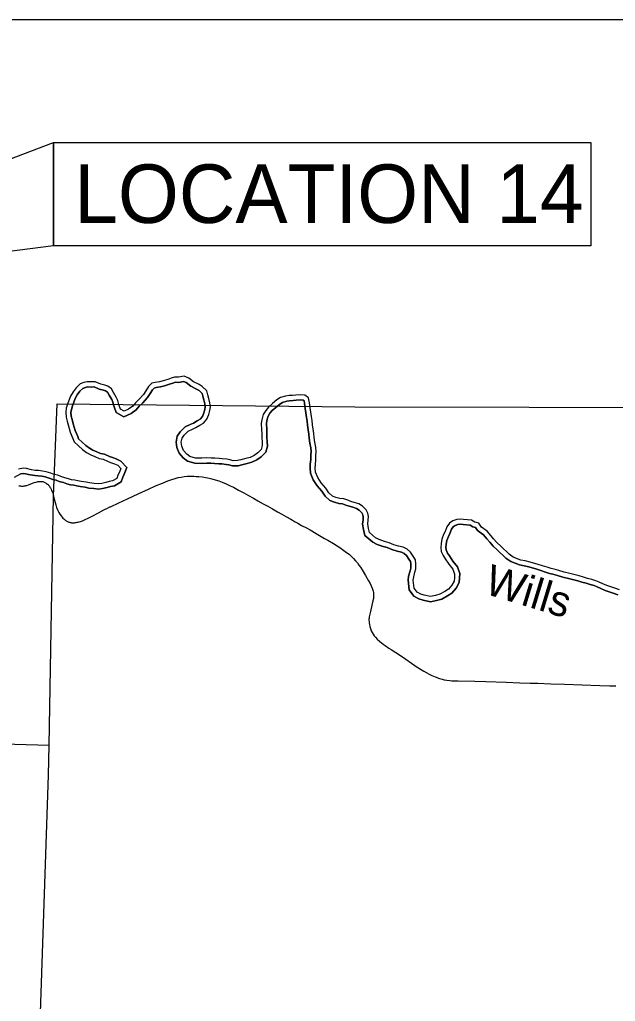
# Model space of a CAD drawing. Extents: x -12.1 to 34, y 0 to 22.
# Drawn here: x 6.151 to 7.88, y 17.456 to 20.306 of the extents above; entities that cross this region are included whole.
import ezdxf

# ---------------------------------------------------------------- set-up
doc = ezdxf.new("R2010")
doc.units = 0
for name, color, linetype in [('BR_P_Gen_Text', 7, 'Continuous'), ('GM_X_Major_River', 7, 'Continuous'), ('GM_X_Major_River_Text', 7, 'Continuous'), ('GM_X_State_Route', 7, 'Continuous'), ('GM_X_Township', 7, 'Continuous'), ('SH_Text', 7, 'Continuous')]:
    doc.layers.add(name, color=color, linetype=linetype)

msp = doc.modelspace()

# ---------------------------------------------------------------- linework, layer by layer
at = {"layer": 'BR_P_Gen_Text'}
for points in [[(6.2488, 19.9493), (6.2488, 19.649), (5.0586, 19.4964)], [(6.2488, 19.9493), (7.8089, 19.9493), (7.8089, 19.649), (6.2488, 19.649)]]:
    msp.add_lwpolyline(points, close=True, dxfattribs=at)
at = {"layer": 'GM_X_Major_River'}
for points in [[(6.8543, 19.0792), (6.8547, 19.0693), (6.8516, 19.0579), (6.8417, 19.0482), (6.8315, 19.0406), (6.8198, 19.0349), (6.8074, 19.0316), (6.7925, 19.0283), (6.7826, 19.0257), (6.7702, 19.0256), (6.7613, 19.0277), (6.7521, 19.0297), (6.7389, 19.0311), (6.7297, 19.0317), (6.7169, 19.0327), (6.7066, 19.0329), (6.6941, 19.0336), (6.6796, 19.0327), (6.6615, 19.0333), (6.6448, 19.0378), (6.6358, 19.0448), (6.6265, 19.0554), (6.6211, 19.0675), (6.6199, 19.0792), (6.622, 19.0906), (6.6283, 19.0995), (6.6403, 19.1114), (6.6523, 19.1171), (6.6625, 19.1218), (6.6735, 19.1287), (6.6841, 19.1348), (6.6943, 19.1459), (6.6999, 19.1595), (6.703, 19.1716), (6.7043, 19.1819), (6.7028, 19.1933), (6.7002, 19.206), (6.6969, 19.217), (6.6943, 19.2288), (6.6804, 19.2411), (6.6715, 19.2464), (6.6554, 19.2548), (6.6415, 19.2657), (6.628, 19.2713), (6.612, 19.2679), (6.6006, 19.2686), (6.5907, 19.2649), (6.5808, 19.2617), (6.567, 19.2573), (6.5564, 19.2547), (6.5443, 19.2525), (6.5344, 19.2503), (6.5242, 19.241), (6.5168, 19.2285), (6.5098, 19.2181), (6.4975, 19.2041), (6.4869, 19.1937), (6.4788, 19.1844), (6.4668, 19.1751), (6.4541, 19.1693), (6.4431, 19.1756), (6.4387, 19.1891), (6.4354, 19.2005), (6.4311, 19.21), (6.4231, 19.2235), (6.417, 19.2344), (6.407, 19.2422), (6.3981, 19.245), (6.386, 19.2477), (6.37, 19.2547), (6.3579, 19.2543), (6.3466, 19.2545), (6.3373, 19.253), (6.326, 19.2483), (6.3144, 19.2372), (6.3056, 19.2254), (6.2983, 19.2129), (6.2937, 19.2004), (6.2899, 19.1897), (6.2861, 19.178), (6.2844, 19.1662), (6.2853, 19.1524), (6.2889, 19.1407), (6.2918, 19.1297), (6.294, 19.119), (6.2977, 19.1084), (6.3053, 19.09), (6.3089, 19.0804), (6.3218, 19.0687), (6.3332, 19.0582), (6.345, 19.0494), (6.3568, 19.0423), (6.3689, 19.0378), (6.3814, 19.0322), (6.3928, 19.0302), (6.4056, 19.0242), (6.4148, 19.0207), (6.4255, 19.0169), (6.4355, 19.0124), (6.4445, 19.0028), (6.4403, 18.9925)], [(6.8691, 19.0799), (6.8697, 19.0676), (6.8649, 19.0501), (6.8514, 19.0368), (6.8393, 19.0279), (6.8251, 19.0209), (6.811, 19.0171), (6.796, 19.0138), (6.7846, 19.0108), (6.7685, 19.0107), (6.758, 19.0132), (6.7497, 19.015), (6.7376, 19.0162), (6.7286, 19.0169), (6.7161, 19.0178), (6.706, 19.0181), (6.6942, 19.0187), (6.6798, 19.0178), (6.6593, 19.0185), (6.6379, 19.0242), (6.6255, 19.034), (6.6139, 19.0473), (6.6065, 19.0636), (6.6049, 19.0798), (6.6079, 19.0965), (6.6169, 19.1092), (6.6316, 19.1237), (6.646, 19.1306), (6.6555, 19.135), (6.6658, 19.1414), (6.6747, 19.1466), (6.6815, 19.154), (6.6857, 19.1642), (6.6883, 19.1744), (6.6893, 19.1819), (6.6881, 19.1908), (6.6858, 19.2024), (6.6825, 19.2133), (6.6808, 19.2208), (6.6716, 19.229), (6.6642, 19.2334), (6.6473, 19.2422), (6.6339, 19.2527), (6.6265, 19.2558), (6.6131, 19.253), (6.6029, 19.2535), (6.5956, 19.2509), (6.5854, 19.2475), (6.571, 19.243), (6.5595, 19.2402), (6.5473, 19.2379), (6.5415, 19.2366), (6.5359, 19.2315), (6.5294, 19.2205), (6.5216, 19.209), (6.5083, 19.1939), (6.4978, 19.1836), (6.4891, 19.1736), (6.4746, 19.1623), (6.4533, 19.1526), (6.4307, 19.1656), (6.4245, 19.1847), (6.4214, 19.1953), (6.4178, 19.2032), (6.4102, 19.2161), (6.4055, 19.2246), (6.4, 19.2288), (6.3942, 19.2306), (6.3813, 19.2335), (6.3671, 19.2397), (6.358, 19.2394), (6.3476, 19.2396), (6.3414, 19.2386), (6.3343, 19.2357), (6.3256, 19.2273), (6.318, 19.2172), (6.3118, 19.2066), (6.3077, 19.1954), (6.304, 19.185), (6.3007, 19.1746), (6.2994, 19.1656), (6.3, 19.1551), (6.3032, 19.1448), (6.3063, 19.1331), (6.3084, 19.123), (6.3116, 19.1136), (6.3191, 19.0954), (6.3216, 19.089), (6.3318, 19.0797), (6.3428, 19.0696), (6.3533, 19.0617), (6.3633, 19.0558), (6.3746, 19.0516), (6.3858, 19.0465), (6.3973, 19.0445), (6.4113, 19.038), (6.42, 19.0347), (6.4311, 19.0307), (6.4443, 19.0247), (6.4618, 19.0061), (6.4541, 18.9869)], [(6.4539, 18.9865), (6.4618, 19.0061), (6.4443, 19.0247), (6.4311, 19.0307), (6.42, 19.0347), (6.4113, 19.038), (6.3973, 19.0445), (6.3858, 19.0465), (6.3746, 19.0516), (6.3633, 19.0558), (6.3533, 19.0617), (6.3428, 19.0696), (6.3318, 19.0797), (6.3216, 19.089), (6.3191, 19.0954), (6.3116, 19.1136), (6.3084, 19.123), (6.3063, 19.1331), (6.3032, 19.1448), (6.3, 19.1551), (6.2994, 19.1656), (6.3007, 19.1746), (6.304, 19.185), (6.3077, 19.1954), (6.3118, 19.2066), (6.318, 19.2172), (6.3256, 19.2273), (6.3343, 19.2357), (6.3414, 19.2386), (6.3476, 19.2396), (6.358, 19.2394), (6.3671, 19.2397), (6.3813, 19.2335), (6.3942, 19.2306), (6.4, 19.2288), (6.4055, 19.2246), (6.4102, 19.2161), (6.4178, 19.2032), (6.4214, 19.1953), (6.4245, 19.1847), (6.4307, 19.1656), (6.4533, 19.1526), (6.4746, 19.1623), (6.4891, 19.1736), (6.4978, 19.1836), (6.5083, 19.1939), (6.5216, 19.209), (6.5294, 19.2205), (6.5359, 19.2315), (6.5415, 19.2366), (6.5473, 19.2379), (6.5595, 19.2402), (6.571, 19.243), (6.5854, 19.2475), (6.5956, 19.2509), (6.6029, 19.2535), (6.6131, 19.253), (6.6265, 19.2558), (6.6339, 19.2527), (6.6473, 19.2422), (6.6642, 19.2334), (6.6716, 19.229), (6.6808, 19.2208), (6.6825, 19.2133), (6.6858, 19.2024), (6.6881, 19.1908), (6.6893, 19.1819), (6.6883, 19.1744), (6.6857, 19.1642), (6.6815, 19.154), (6.6747, 19.1466), (6.6658, 19.1414), (6.6555, 19.135), (6.646, 19.1306), (6.6316, 19.1237), (6.6169, 19.1092), (6.6079, 19.0965), (6.6049, 19.0798), (6.6065, 19.0636), (6.6139, 19.0473), (6.6255, 19.034), (6.6379, 19.0242), (6.6593, 19.0185), (6.6798, 19.0178), (6.6942, 19.0187), (6.706, 19.0181), (6.7161, 19.0178), (6.7286, 19.0169), (6.7376, 19.0162), (6.7497, 19.015), (6.758, 19.0132), (6.7685, 19.0107), (6.7846, 19.0108), (6.796, 19.0138), (6.811, 19.0171), (6.8251, 19.0209), (6.8393, 19.0279), (6.8514, 19.0368), (6.8649, 19.0501), (6.8697, 19.0676), (6.8691, 19.0799)], [(7.4394, 18.855), (7.4298, 18.856), (7.4199, 18.8553), (7.4078, 18.8509), (7.3983, 18.8444), (7.3906, 18.8333), (7.3857, 18.8201), (7.3815, 18.8109), (7.3767, 18.7977), (7.3739, 18.7856), (7.3729, 18.7735), (7.3741, 18.7624), (7.3799, 18.75), (7.386, 18.7408), (7.3964, 18.7253), (7.4086, 18.7104), (7.4133, 18.6962), (7.4127, 18.6859), (7.4117, 18.676), (7.4054, 18.6642), (7.3956, 18.6524), (7.3853, 18.6455), (7.3709, 18.6376), (7.3574, 18.6343), (7.3436, 18.631), (7.3254, 18.6348), (7.3151, 18.6379), (7.3048, 18.6438), (7.2958, 18.6559), (7.2935, 18.679), (7.2945, 18.6879), (7.2983, 18.7021), (7.3007, 18.7114), (7.3009, 18.7263), (7.3001, 18.7377), (7.2929, 18.748), (7.285, 18.7596), (7.2757, 18.7688), (7.2639, 18.7744), (7.2501, 18.7771), (7.2366, 18.7817), (7.223, 18.7872), (7.2102, 18.7911), (7.1945, 18.7963), (7.1838, 18.8015), (7.1663, 18.8167), (7.163, 18.8291), (7.1612, 18.8419), (7.1625, 18.8529), (7.1631, 18.8636), (7.1613, 18.8732), (7.1566, 18.8831), (7.1458, 18.8937), (7.1351, 18.9004), (7.1219, 18.9045), (7.1123, 18.9073), (7.1031, 18.9108), (7.0913, 18.9153), (7.08, 18.9163), (7.0686, 18.9191), (7.0593, 18.9226), (7.0486, 18.9324), (7.0396, 18.9462), (7.0263, 18.9614), (7.0159, 18.977), (7.0098, 18.9926), (7.0086, 19.0043), (7.0092, 19.0146), (7.0105, 19.0281), (7.0104, 19.0406), (7.0114, 19.0516), (7.0109, 19.0648), (7.008, 19.079), (7.0057, 19.0928), (7.0046, 19.1046), (7.0027, 19.117), (7.0008, 19.1301), (6.9997, 19.1422), (6.9982, 19.1536), (6.9959, 19.1667), (6.9944, 19.1791), (6.9925, 19.1937), (6.9895, 19.2083), (6.9788, 19.2156), (6.9667, 19.2173), (6.9522, 19.2161), (6.943, 19.215), (6.933, 19.2146), (6.9228, 19.2131), (6.9082, 19.2087), (6.8973, 19.2026), (6.8842, 19.1918), (6.8726, 19.1814), (6.8649, 19.1717), (6.8579, 19.1593), (6.8534, 19.1446), (6.852, 19.1347), (6.8529, 19.1151), (6.8537, 19.1041), (6.8538, 19.0934), (6.8543, 19.0792)], [(7.4379, 18.8402), (7.4296, 18.8411), (7.423, 18.8406), (7.4147, 18.8375), (7.4089, 18.8337), (7.4039, 18.8264), (7.3995, 18.8145), (7.3953, 18.8052), (7.391, 18.7934), (7.3887, 18.7833), (7.3879, 18.7736), (7.3886, 18.7665), (7.3929, 18.7573), (7.3984, 18.7491), (7.4084, 18.7342), (7.4219, 18.7177), (7.4284, 18.6982), (7.4276, 18.6847), (7.4262, 18.6716), (7.4178, 18.6558), (7.4056, 18.6412), (7.3931, 18.6328), (7.3763, 18.6236), (7.3609, 18.6198), (7.3438, 18.6157), (7.3218, 18.6203), (7.3092, 18.6241), (7.2947, 18.6325), (7.2814, 18.6503), (7.2785, 18.6791), (7.2798, 18.6906), (7.2839, 18.7059), (7.2858, 18.7134), (7.286, 18.7259), (7.2855, 18.7325), (7.2807, 18.7395), (7.2735, 18.7501), (7.267, 18.7565), (7.2592, 18.7602), (7.2463, 18.7627), (7.2313, 18.7677), (7.218, 18.7732), (7.2057, 18.7769), (7.1889, 18.7825), (7.1756, 18.789), (7.1531, 18.8084), (7.1484, 18.8261), (7.1461, 18.8417), (7.1477, 18.8543), (7.1481, 18.8626), (7.147, 18.8685), (7.1442, 18.8744), (7.1365, 18.882), (7.1288, 18.8868), (7.1176, 18.8903), (7.1076, 18.8932), (7.0978, 18.8969), (7.0879, 18.9007), (7.0776, 18.9016), (7.0642, 18.9048), (7.0514, 18.9097), (7.0371, 18.9227), (7.0277, 18.9372), (7.0145, 18.9524), (7.0027, 18.97), (6.9951, 18.9891), (6.9937, 19.004), (6.9944, 19.0158), (6.9956, 19.0288), (6.9955, 19.0412), (6.9965, 19.052), (6.9961, 19.063), (6.9933, 19.0763), (6.991, 19.0909), (6.9898, 19.1027), (6.988, 19.1148), (6.986, 19.1284), (6.9849, 19.1405), (6.9834, 19.1513), (6.9812, 19.1646), (6.9796, 19.1773), (6.9778, 19.1913), (6.9762, 19.1994), (6.9733, 19.2014), (6.9663, 19.2024), (6.9537, 19.2013), (6.9442, 19.2002), (6.9344, 19.1998), (6.926, 19.1985), (6.9141, 19.1949), (6.9057, 19.1902), (6.8939, 19.1805), (6.8834, 19.1711), (6.8773, 19.1634), (6.8716, 19.1534), (6.868, 19.1414), (6.867, 19.134), (6.8678, 19.116), (6.8686, 19.1047), (6.8687, 19.0937), (6.8691, 19.0797)], [(6.8691, 19.0799), (6.8687, 19.0937), (6.8686, 19.1047), (6.8678, 19.116), (6.867, 19.134), (6.868, 19.1414), (6.8716, 19.1534), (6.8773, 19.1634), (6.8834, 19.1711), (6.8939, 19.1805), (6.9057, 19.1902), (6.9141, 19.1949), (6.926, 19.1985), (6.9344, 19.1998), (6.9442, 19.2002), (6.9537, 19.2013), (6.9663, 19.2024), (6.9733, 19.2014), (6.9762, 19.1994), (6.9778, 19.1913), (6.9796, 19.1773), (6.9812, 19.1646), (6.9834, 19.1513), (6.9849, 19.1405), (6.986, 19.1284), (6.988, 19.1148), (6.9898, 19.1027), (6.991, 19.0909), (6.9933, 19.0763), (6.9961, 19.063), (6.9965, 19.052), (6.9955, 19.0412), (6.9956, 19.0288), (6.9944, 19.0158), (6.9937, 19.004), (6.9951, 18.9891), (7.0027, 18.97), (7.0145, 18.9524), (7.0277, 18.9372), (7.0371, 18.9227), (7.0514, 18.9097), (7.0642, 18.9048), (7.0776, 18.9016), (7.0879, 18.9007), (7.0978, 18.8969), (7.1076, 18.8932), (7.1176, 18.8903), (7.1288, 18.8868), (7.1365, 18.882), (7.1442, 18.8744), (7.147, 18.8685), (7.1481, 18.8626), (7.1477, 18.8543), (7.1461, 18.8417), (7.1484, 18.8261), (7.1531, 18.8084), (7.1756, 18.789), (7.1889, 18.7825), (7.2057, 18.7769), (7.218, 18.7732), (7.2313, 18.7677), (7.2463, 18.7627), (7.2592, 18.7602), (7.267, 18.7565), (7.2735, 18.7501), (7.2807, 18.7395), (7.2855, 18.7325), (7.286, 18.7259), (7.2858, 18.7134), (7.2839, 18.7059), (7.2798, 18.6906), (7.2785, 18.6791), (7.2814, 18.6503), (7.2947, 18.6325), (7.3092, 18.6241), (7.3218, 18.6203), (7.3438, 18.6157), (7.3609, 18.6198), (7.3763, 18.6236), (7.3931, 18.6328), (7.4056, 18.6412), (7.4178, 18.6558), (7.4262, 18.6716), (7.4276, 18.6847), (7.4284, 18.6982), (7.4219, 18.7177), (7.4084, 18.7342), (7.3984, 18.7491), (7.3929, 18.7573), (7.3886, 18.7665), (7.3879, 18.7736), (7.3887, 18.7833), (7.391, 18.7934), (7.3953, 18.8052), (7.3995, 18.8145), (7.4039, 18.8264), (7.4089, 18.8337), (7.4147, 18.8375), (7.423, 18.8406), (7.4296, 18.8411), (7.4378, 18.8403)], [(6.1543, 18.9874), (6.1348, 18.9765)], [(6.4403, 18.9925), (6.4361, 18.9836), (6.433, 18.9739), (6.4206, 18.9667), (6.4103, 18.9649), (6.4011, 18.962), (6.3891, 18.9594), (6.3798, 18.9582), (6.3674, 18.9592), (6.3535, 18.9609), (6.3436, 18.9629), (6.329, 18.9653), (6.3194, 18.9674), (6.3105, 18.9691), (6.3013, 18.9701), (6.2924, 18.9725), (6.2821, 18.9763), (6.2703, 18.9794), (6.2614, 18.9833), (6.2511, 18.9853), (6.2415, 18.9892), (6.228, 18.9937), (6.2173, 18.9954), (6.2056, 18.9967), (6.1956, 18.997), (6.1846, 18.9987), (6.1704, 19.0025), (6.1615, 19.0039), (6.1469, 19.0007)], [(6.4538, 18.9862), (6.45, 18.9781), (6.4454, 18.964), (6.4258, 18.9526), (6.4139, 18.9504), (6.4049, 18.9476), (6.3915, 18.9447), (6.3802, 18.9433), (6.3659, 18.9444), (6.3511, 18.9462), (6.3409, 18.9483), (6.3263, 18.9507), (6.3164, 18.9528), (6.3083, 18.9544), (6.2985, 18.9554), (6.2878, 18.9583), (6.2776, 18.9621), (6.2654, 18.9653), (6.257, 18.969), (6.2469, 18.971), (6.2364, 18.9752), (6.2244, 18.9792), (6.2153, 18.9807), (6.2045, 18.9819), (6.1943, 18.9822), (6.1815, 18.9841), (6.1673, 18.9879), (6.1617, 18.9888), (6.1543, 18.9874)], [(6.1543, 18.9874), (6.1617, 18.9888), (6.1673, 18.9879), (6.1815, 18.9841), (6.1943, 18.9822), (6.2045, 18.9819), (6.2153, 18.9807), (6.2244, 18.9792), (6.2364, 18.9752), (6.2469, 18.971), (6.257, 18.969), (6.2654, 18.9653), (6.2776, 18.9621), (6.2878, 18.9583), (6.2985, 18.9554), (6.3083, 18.9544), (6.3164, 18.9528), (6.3263, 18.9507), (6.3409, 18.9483), (6.3511, 18.9462), (6.3659, 18.9444), (6.3802, 18.9433), (6.3915, 18.9447), (6.4049, 18.9476), (6.4139, 18.9504), (6.4258, 18.9526), (6.4454, 18.964), (6.45, 18.9781), (6.4539, 18.9865)], [(7.8919, 18.6505), (7.8788, 18.655), (7.867, 18.6592), (7.8553, 18.663), (7.8439, 18.6679), (7.8328, 18.6731), (7.8232, 18.677), (7.8115, 18.6808), (7.7994, 18.6839), (7.7873, 18.6874), (7.7748, 18.6912), (7.7634, 18.6943), (7.7478, 18.6981), (7.7318, 18.7022), (7.7161, 18.7064), (7.7022, 18.7105), (7.6933, 18.7126), (7.6819, 18.7164), (7.6681, 18.7206), (7.656, 18.7244), (7.6325, 18.7313), (7.6186, 18.7348), (7.6054, 18.7372), (7.5837, 18.7459), (7.5716, 18.754), (7.5476, 18.7776), (7.5361, 18.7882), (7.5265, 18.7985), (7.5186, 18.808), (7.5075, 18.8214), (7.491, 18.833), (7.4835, 18.8444), (7.4718, 18.8475), (7.4628, 18.8527), (7.4394, 18.855)], [(7.4378, 18.8403), (7.4581, 18.8383), (7.466, 18.8336), (7.4742, 18.8314), (7.4802, 18.8225), (7.4973, 18.8104), (7.5071, 18.7985), (7.5153, 18.7886), (7.5257, 18.7776), (7.5373, 18.7669), (7.5621, 18.7424), (7.5767, 18.7327), (7.6013, 18.7228), (7.6155, 18.7202), (7.6286, 18.717), (7.6516, 18.7102), (7.6637, 18.7064), (7.6774, 18.7022), (7.6893, 18.6983), (7.6984, 18.6962), (7.7121, 18.6921), (7.728, 18.6878), (7.7441, 18.6837), (7.7597, 18.6799), (7.7707, 18.6769), (7.783, 18.6731), (7.7955, 18.6695), (7.8073, 18.6665), (7.8181, 18.663), (7.8269, 18.6595), (7.8377, 18.6543), (7.85, 18.649), (7.8622, 18.6451), (7.8739, 18.6409), (7.8873, 18.6363)], [(7.8873, 18.6363), (7.8739, 18.6409), (7.8622, 18.6451), (7.85, 18.649), (7.8377, 18.6543), (7.8269, 18.6595), (7.8181, 18.663), (7.8073, 18.6665), (7.7955, 18.6695), (7.783, 18.6731), (7.7707, 18.6769), (7.7597, 18.6799), (7.7441, 18.6837), (7.728, 18.6878), (7.7121, 18.6921), (7.6984, 18.6962), (7.6893, 18.6983), (7.6774, 18.7022), (7.6637, 18.7064), (7.6516, 18.7102), (7.6286, 18.717), (7.6155, 18.7202), (7.6013, 18.7228), (7.5767, 18.7327), (7.5621, 18.7424), (7.5373, 18.7669), (7.5257, 18.7776), (7.5153, 18.7886), (7.5071, 18.7985), (7.4973, 18.8104), (7.4802, 18.8225), (7.4742, 18.8314), (7.466, 18.8336), (7.4581, 18.8383), (7.4379, 18.8402)]]:
    msp.add_lwpolyline(points, dxfattribs=at)
at = {"layer": 'GM_X_State_Route'}
for points in [[(6.1487, 18.953), (6.151, 18.9525), (6.1532, 18.9522), (6.1557, 18.9519), (6.1583, 18.9519), (6.1611, 18.952), (6.1637, 18.9522), (6.1663, 18.9526), (6.1687, 18.9531), (6.1713, 18.9538), (6.1767, 18.9556), (6.1931, 18.9619), (6.1987, 18.9637), (6.2012, 18.9644), (6.2038, 18.9649), (6.2059, 18.9652), (6.208, 18.9654), (6.2096, 18.9654), (6.2116, 18.9654), (6.2136, 18.9653), (6.2157, 18.9651), (6.2177, 18.9647), (6.2198, 18.9642), (6.2221, 18.9634), (6.2241, 18.9626), (6.2259, 18.9617), (6.2274, 18.9607), (6.229, 18.9597), (6.2313, 18.9579), (6.2331, 18.9563), (6.2347, 18.9545), (6.236, 18.9528), (6.2372, 18.9512), (6.2385, 18.9492), (6.2398, 18.9472), (6.241, 18.9449), (6.2422, 18.9425), (6.2434, 18.9395), (6.2446, 18.9365), (6.2465, 18.9309), (6.2489, 18.9231), (6.2493, 18.9217)], [(6.2493, 18.9217), (6.2522, 18.9106), (6.2554, 18.8976), (6.2579, 18.8893), (6.261, 18.8813), (6.2645, 18.8747), (6.267, 18.8707), (6.2707, 18.8656), (6.274, 18.8616), (6.2764, 18.859), (6.2784, 18.8571), (6.2801, 18.8556), (6.2819, 18.8541), (6.2836, 18.8528), (6.2856, 18.8514), (6.2875, 18.8501), (6.2898, 18.8489), (6.2916, 18.8481), (6.2933, 18.8474), (6.2953, 18.8467), (6.2969, 18.8463), (6.299, 18.8458), (6.3014, 18.8455), (6.3038, 18.8454), (6.3059, 18.8453), (6.3079, 18.8454), (6.3099, 18.8456), (6.3122, 18.8459), (6.3145, 18.8462), (6.3175, 18.8468), (6.3207, 18.8475), (6.3236, 18.8483), (6.3268, 18.8493), (6.3298, 18.8503), (6.3328, 18.8514), (6.3408, 18.8547), (6.3497, 18.8589), (6.3611, 18.8647), (6.3796, 18.8745), (6.3951, 18.8826), (6.4059, 18.8882), (6.4126, 18.8912), (6.4144, 18.8921), (6.4386, 18.9034), (6.4639, 18.9152), (6.4945, 18.9296), (6.5243, 18.943), (6.5451, 18.9522), (6.5655, 18.9608), (6.5812, 18.9671), (6.5927, 18.9713), (6.6022, 18.9742), (6.6107, 18.9764), (6.6193, 18.9781), (6.628, 18.9794), (6.6367, 18.9802), (6.646, 18.9804), (6.6565, 18.9802), (6.6629, 18.9799), (6.6704, 18.9794), (6.6809, 18.9783), (6.6913, 18.9768), (6.7005, 18.975), (6.7085, 18.9731), (6.718, 18.9703), (6.7285, 18.9668), (6.7389, 18.9629), (6.7497, 18.9584), (6.7619, 18.9529), (6.7714, 18.9483), (6.7863, 18.9404), (6.8011, 18.9322), (6.8148, 18.9247), (6.8296, 18.9164), (6.8423, 18.9093), (6.8576, 18.9008), (6.8708, 18.8934), (6.885, 18.8854), (6.8993, 18.8775), (6.9115, 18.8707), (6.9256, 18.8626), (6.9378, 18.8557), (6.9504, 18.8485), (6.958, 18.8442), (6.9692, 18.8379), (6.9829, 18.8302), (6.9936, 18.8244), (7.0115, 18.8145), (7.036, 18.8001), (7.0455, 18.7945), (7.0616, 18.7851), (7.0725, 18.7783), (7.0802, 18.7732), (7.0879, 18.7679), (7.0996, 18.7595), (7.107, 18.7538), (7.1135, 18.748), (7.1201, 18.7414), (7.126, 18.7349), (7.1312, 18.7286), (7.1357, 18.7225), (7.14, 18.7163), (7.1449, 18.7083), (7.1544, 18.6923), (7.1635, 18.6767), (7.1678, 18.669), (7.1713, 18.6623), (7.1742, 18.6558), (7.1754, 18.6525), (7.1763, 18.6495), (7.1772, 18.6463), (7.1778, 18.6425), (7.1783, 18.6387), (7.1783, 18.6349), (7.1782, 18.631), (7.1779, 18.6282), (7.1775, 18.6252), (7.1763, 18.6182), (7.1735, 18.6063), (7.1688, 18.5876), (7.1671, 18.5803), (7.1654, 18.5718), (7.165, 18.5687), (7.1648, 18.5651), (7.1648, 18.5621), (7.1649, 18.5589), (7.1652, 18.5552), (7.1662, 18.5496), (7.1674, 18.544), (7.1693, 18.5379), (7.1715, 18.532), (7.174, 18.5268), (7.1769, 18.5219), (7.1802, 18.5171), (7.1838, 18.5127), (7.1886, 18.5077), (7.1949, 18.5017), (7.2007, 18.4969), (7.2062, 18.4926), (7.2119, 18.4887), (7.2223, 18.4816), (7.2291, 18.4771), (7.2427, 18.4682), (7.2558, 18.4596), (7.2714, 18.4492), (7.2879, 18.4377), (7.3017, 18.428), (7.3139, 18.42), (7.3238, 18.4141), (7.3324, 18.4092), (7.3391, 18.4058), (7.3475, 18.402), (7.3567, 18.3983), (7.3698, 18.3936), (7.3775, 18.3911), (7.3831, 18.3897), (7.3905, 18.3883), (7.3991, 18.3872), (7.4054, 18.3867), (7.4234, 18.3861), (7.4724, 18.3853), (7.5044, 18.3842), (7.5632, 18.3821), (7.6028, 18.381), (7.6325, 18.3799), (7.6546, 18.3794), (7.6925, 18.3778), (7.732, 18.3763), (7.7838, 18.3744), (7.8351, 18.3729), (7.8636, 18.372), (7.8817, 18.3717)]]:
    msp.add_lwpolyline(points, dxfattribs=at)
at = {"layer": 'GM_X_Township'}
for points in [[(6.2076, 17.3082), (6.2339, 18.1122), (6.2359, 18.1999), (6.2491, 18.9222), (6.2599, 19.1909), (7.1234, 19.1821), (8.1356, 19.1805)], [(5.7702, 18.2131), (6.2359, 18.1999)]]:
    msp.add_lwpolyline(points, dxfattribs=at)
at = {"layer": 'SH_Text'}
msp.add_lwpolyline([(2.8817, 20.3063), (10.5897, 20.3063), (10.5897, 10.9773), (2.8817, 10.9773)], close=True, dxfattribs=at)

# ---------------------------------------------------------------- texts
at = {"layer": 'BR_P_Gen_Text'}
msp.add_text('LOCATION 14', height=0.17, dxfattribs=at).set_placement((6.3095, 19.7159))
at = {"layer": 'GM_X_Major_River_Text'}
msp.add_text('Wills', height=0.08878, rotation=343.0568, dxfattribs=at).set_placement((7.4958, 18.6408))

doc.saveas('drawing.dxf')
